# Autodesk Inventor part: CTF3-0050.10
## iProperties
Shininess: 64.0
Length Units: 11269
Angle Units: 11279
Time Units: 11290
Mass Units: 11283
Length Display Precision: 3
Angle Display Precision: 2
Compacted: True
Part Number: CTF3-0050.10
Document SubType Name: Modeling
Created: 2003-11
Designer: Lollo
Density: 0.0
Volumn: 0.0
Area: 0.0
PropertySet Name: Model Information
Control State: 0
Master: False
Checked Out: False
Author: Lollo
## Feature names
1. Estrusione1 [Extrusion]
2. Foro1 [Hole]
